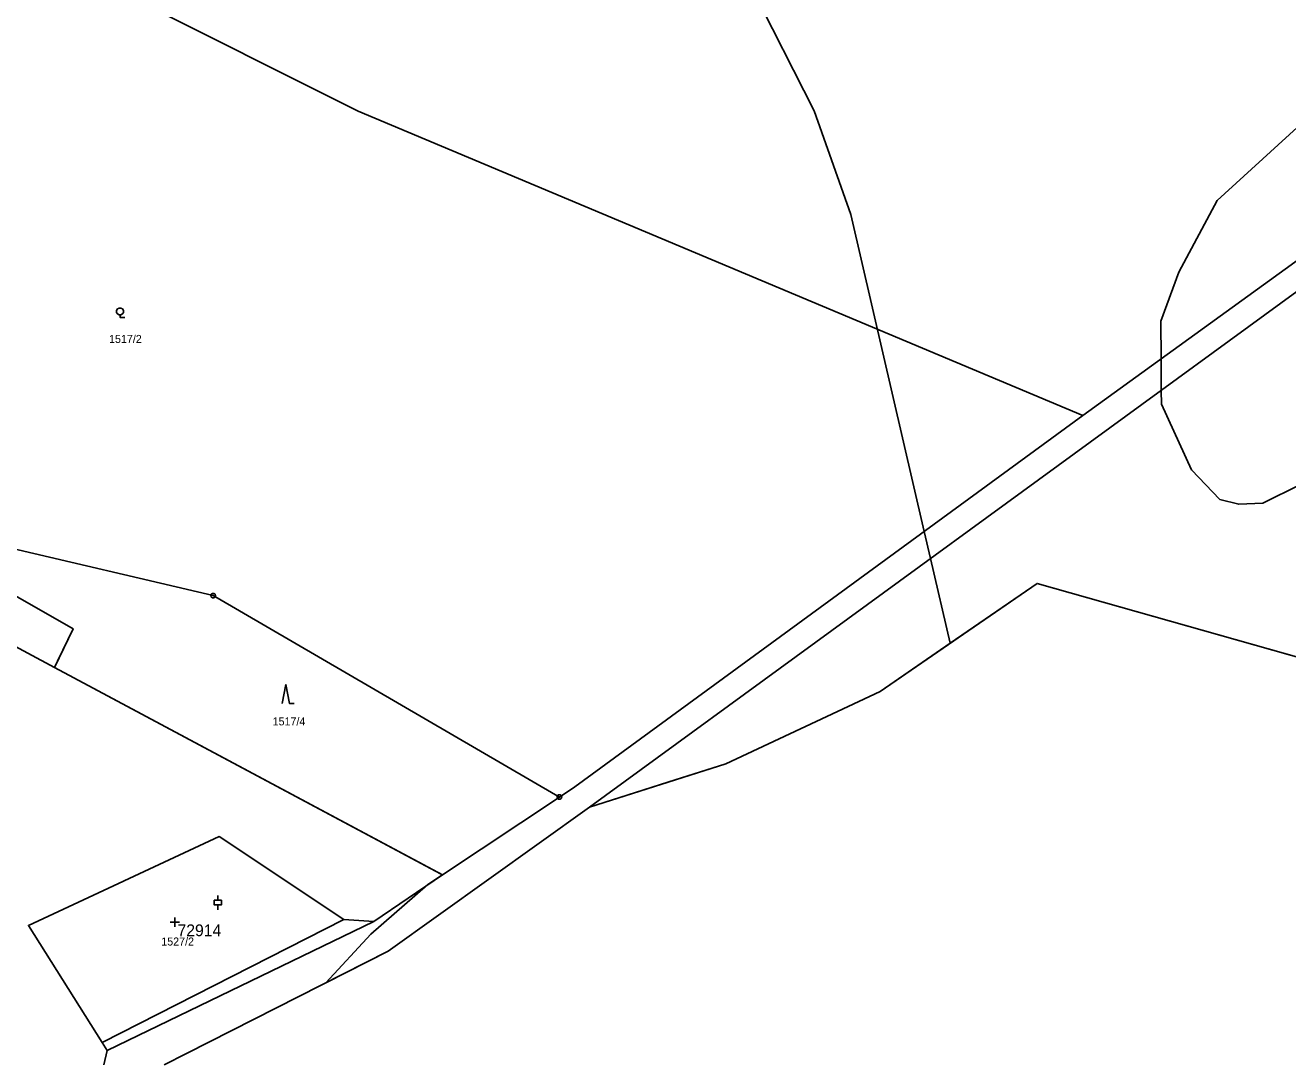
# Model space of a CAD drawing. Extents: x -779618 to -776429, y -1144546 to -1143350.
# Drawn here: x -777926.1 to -777658, y -1144546.2 to -1144325.3 of the extents above; entities that cross this region are included whole.
import ezdxf

# ---------------------------------------------------------------- set-up
doc = ezdxf.new("R2010")
doc.units = 0
for name, color, linetype in [('1', 7, 'Continuous'), ('11', 7, 'Continuous'), ('2', 7, 'Continuous'), ('3', 7, 'Continuous'), ('4', 7, 'Continuous'), ('8', 7, 'Continuous')]:
    doc.layers.add(name, color=color, linetype=linetype)

msp = doc.modelspace()

# ---------------------------------------------------------------- linework, layer by layer
at = {"layer": '1'}
for p, q in [((-777855.44, -1144343.58), (-778011.12, -1144265.48)), ((-777701.52, -1144408.27), (-777855.44, -1144343.58)), ((-777701.52, -1144408.27), (-777611.89, -1144343.36)), ((-777609.53, -1144347.96), (-777806.32, -1144491.5)), ((-777809.4, -1144487.14), (-777701.52, -1144408.27)), ((-777959.22, -1144428.87), (-777915.96, -1144453.57)), ((-777919.9, -1144461.76), (-777972.59, -1144433.55)), ((-777886.2, -1144446.52), (-777933.46, -1144435.4)), ((-777711.22, -1144443.91), (-777744.58, -1144466.86)), ((-777632.62, -1144466.21), (-777711.22, -1144443.91)), ((-777812.68, -1144489.32), (-777886.2, -1144446.52)), ((-777915.96, -1144453.57), (-777919.9, -1144461.76)), ((-777919.9, -1144461.76), (-777837.53, -1144505.84)), ((-777744.58, -1144466.86), (-777777.33, -1144482.23)), ((-777789.46, -1144486.11), (-777777.33, -1144482.23)), ((-777812.68, -1144489.32), (-777809.4, -1144487.14)), ((-777806.32, -1144491.5), (-777796.49, -1144488.36)), ((-777796.49, -1144488.36), (-777789.46, -1144486.11)), ((-777837.53, -1144505.84), (-777812.68, -1144489.32)), ((-777849.03, -1144522.06), (-777806.32, -1144491.5)), ((-777925.45, -1144516.58), (-777884.97, -1144497.71)), ((-777858.43, -1144515.33), (-777884.97, -1144497.71)), ((-777852.08, -1144515.76), (-777837.53, -1144505.84)), ((-777925.45, -1144516.58), (-777909.78, -1144541.48)), ((-777908.73, -1144543.17), (-777852.08, -1144515.76)), ((-777852.08, -1144515.76), (-777858.43, -1144515.33)), ((-777891.86, -1144543.78), (-777849.03, -1144522.06)), ((-777909.78, -1144541.48), (-777908.73, -1144543.17)), ((-777909.43, -1144546.2), (-777908.73, -1144543.17)), ((-777896.64, -1144546.2), (-777891.86, -1144543.78))]:
    msp.add_line(p, q, dxfattribs=at)
at = {"layer": '11'}
for points in [[(-777980.08, -1144250.42), (-777857.01, -1144268.43), (-777833.71, -1144275.88), (-777811.46, -1144284.49), (-777794.21, -1144294.72), (-777783.45, -1144302.7), (-777771.8, -1144317.41), (-777758.56, -1144343.51), (-777750.82, -1144365.57), (-777735.2, -1144432.89), (-777733.86, -1144438.65), (-777729.69, -1144456.62)], [(-778154.97, -1144337.7), (-778107.37, -1144362.89), (-778074.01, -1144376.57), (-778033.95, -1144386.03), (-778011.09, -1144394.05), (-777964.59, -1144417.15), (-777959.22, -1144428.87), (-777915.96, -1144453.57), (-777919.28, -1144460.47), (-777919.9, -1144461.76), (-777837.94, -1144505.62), (-777837.53, -1144505.84), (-777840.59, -1144507.92), (-777852.72, -1144518.48), (-777862.28, -1144528.78)], [(-777655.27, -1144422.89), (-777663.32, -1144426.86), (-777668.39, -1144427.1), (-777672.42, -1144426.06), (-777678.45, -1144419.77), (-777684.83, -1144405.81), (-777684.85, -1144402.9), (-777684.89, -1144396.23), (-777684.95, -1144388.21), (-777681.13, -1144377.81), (-777673.02, -1144362.58), (-777656.01, -1144347.08)], [(-777729.69, -1144456.62), (-777711.22, -1144443.91), (-777632.62, -1144466.21), (-777494.51, -1144511.08), (-777414.7, -1144542.12), (-777402.15, -1144546.2)], [(-777862.28, -1144528.78), (-777849.03, -1144522.06), (-777806.32, -1144491.5), (-777777.33, -1144482.23), (-777744.58, -1144466.86), (-777729.69, -1144456.62)]]:
    msp.add_lwpolyline(points, dxfattribs=at)
msp.add_lwpolyline([(-777909.78, -1144541.48), (-777908.73, -1144543.17), (-777852.08, -1144515.76), (-777858.43, -1144515.33), (-777884.97, -1144497.71), (-777925.45, -1144516.58)], close=True, dxfattribs=at)
at = {"layer": '3'}
for p, q in [((-777885.23, -1144511.25), (-777885.23, -1144510.25)), ((-777894.36, -1144516.88), (-777894.36, -1144514.88)), ((-777895.36, -1144515.88), (-777893.36, -1144515.88))]:
    msp.add_line(p, q, dxfattribs=at)
for points in [[(-777906, -1144386.86), (-777906.19, -1144386.86), (-777906.53, -1144386.67), (-777906.72, -1144386.33), (-777906.72, -1144385.94), (-777906.53, -1144385.6), (-777906.19, -1144385.41), (-777905.8, -1144385.41), (-777905.46, -1144385.6), (-777905.27, -1144385.94), (-777905.27, -1144386.33), (-777905.46, -1144386.67), (-777905.8, -1144386.86), (-777905.99, -1144386.86), (-777905.99, -1144387.39), (-777904.99, -1144387.39)], [(-777871.53, -1144469.43), (-777870.78, -1144465.43), (-777870.03, -1144469.43), (-777869.03, -1144469.43)], [(-777885.23, -1144513.25), (-777885.23, -1144512.25), (-777885.98, -1144512.25), (-777885.98, -1144511.25), (-777885.23, -1144511.25), (-777884.48, -1144511.25), (-777884.48, -1144512.25), (-777885.23, -1144512.25)]]:
    msp.add_lwpolyline(points, dxfattribs=at)
at = {"layer": '4'}
msp.add_line((-777909.78, -1144541.48), (-777858.43, -1144515.33), dxfattribs=at)
at = {"layer": '8'}
for p, q in [((-777886.32, -1144446.52), (-777886.08, -1144446.52)), ((-777812.8, -1144489.32), (-777812.56, -1144489.32))]:
    msp.add_line(p, q, dxfattribs=at)
for points in [[(-777886.05, -1144446.04), (-777885.8, -1144446.22), (-777885.7, -1144446.51), (-777885.8, -1144446.8), (-777886.05, -1144446.98), (-777886.36, -1144446.98), (-777886.61, -1144446.8), (-777886.71, -1144446.51), (-777886.61, -1144446.22), (-777886.36, -1144446.04)], [(-777812.53, -1144488.84), (-777812.28, -1144489.02), (-777812.18, -1144489.31), (-777812.28, -1144489.6), (-777812.53, -1144489.78), (-777812.84, -1144489.78), (-777813.09, -1144489.6), (-777813.19, -1144489.31), (-777813.09, -1144489.02), (-777812.84, -1144488.84)]]:
    msp.add_lwpolyline(points, close=True, dxfattribs=at)

# ---------------------------------------------------------------- texts
at = {"layer": '11'}
msp.add_text('72914', height=2.5, dxfattribs=at).set_placement((-777893.79, -1144518.88))
at = {"layer": '2'}
for s, p in [('1517/2', (-777908.33, -1144392.83)), ('1517/4', (-777873.59, -1144474.09)), ('1527/2', (-777897.24, -1144520.86))]:
    msp.add_text(s, height=1.7, dxfattribs=at).set_placement(p)

doc.saveas('drawing.dxf')
